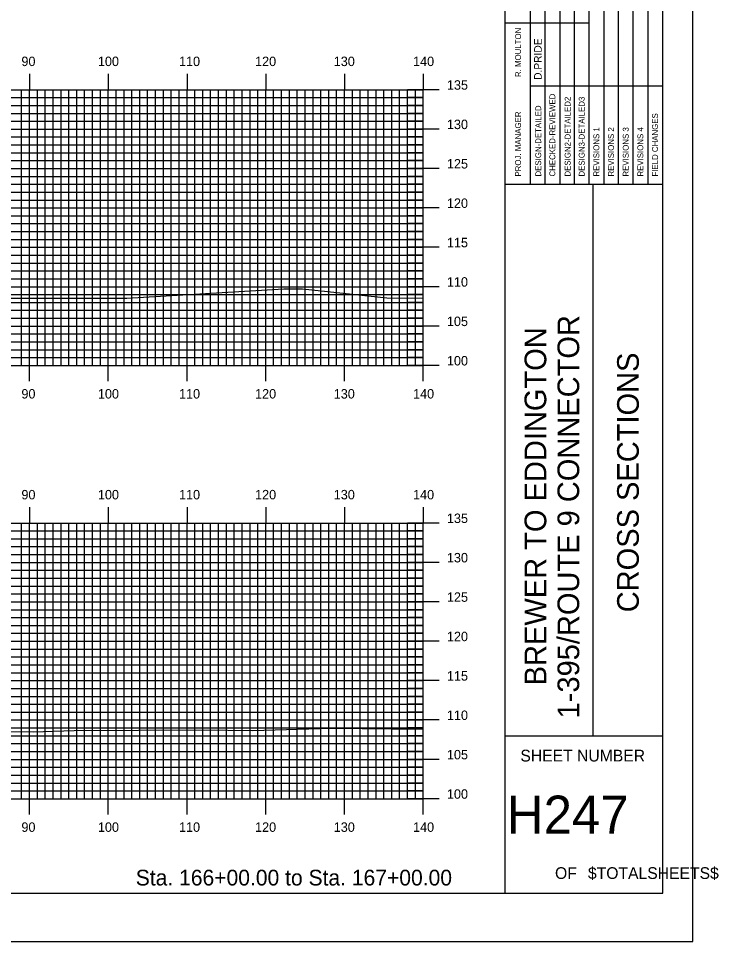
# Model space of a CAD drawing. Extents: x 1781467 to 1781810, y 442591 to 442811.
# Drawn here: x 1781721 to 1781809.9, y 442590.5 to 442707.7 of the extents above; entities that cross this region are included whole.
import ezdxf

# ---------------------------------------------------------------- set-up
doc = ezdxf.new("R2010")
doc.units = 0
for name, color, linetype in [('BORDER', 7, 'Continuous'), ('H_V ANNOTATION', 7, 'Continuous'), ('MAJOR', 7, 'Continuous'), ('MINOR', 7, 'Continuous'), ('PLOT BOUNDARY', 7, 'Continuous'), ('S_Roadway_Centerline', 7, 'Continuous')]:
    doc.layers.add(name, color=color, linetype=linetype)

msp = doc.modelspace()

# ---------------------------------------------------------------- linework, layer by layer
at = {"layer": 'BORDER'}
for p, q in [((1781782.81, 442596.67), (1781782.81, 442806.67)), ((1781782.81, 442686.67), (1781802.81, 442686.67)), ((1781793.99, 442616.67), (1781793.99, 442686.67)), ((1781782.81, 442616.67), (1781802.81, 442616.67))]:
    msp.add_line(p, q, dxfattribs=at)
msp.add_lwpolyline([(1781482.81, 442596.67), (1781802.81, 442596.67), (1781802.81, 442806.67), (1781482.81, 442806.67)], close=True, dxfattribs=at)
for points in [[(1781787.9, 442686.68), (1781787.9, 442721.67)], [(1781789.77, 442721.67), (1781789.77, 442686.68)], [(1781791.63, 442686.68), (1781791.63, 442721.67)], [(1781793.49, 442686.68), (1781793.49, 442721.67)], [(1781795.36, 442686.68), (1781795.36, 442721.67)], [(1781797.22, 442686.68), (1781797.22, 442721.67)], [(1781799.08, 442686.68), (1781799.08, 442721.67)], [(1781800.95, 442686.68), (1781800.95, 442721.67)], [(1781786.04, 442686.68), (1781786.04, 442720.26)], [(1781782.81, 442707.17), (1781786.04, 442707.17)], [(1781786.04, 442707.17), (1781793.49, 442707.17)], [(1781786.04, 442699.17), (1781802.81, 442699.17)]]:
    msp.add_lwpolyline(points, dxfattribs=at)
at = {"layer": 'MAJOR'}
for p, q in [((1781722.41, 442700.67), (1781722.41, 442698.67)), ((1781732.41, 442700.67), (1781732.41, 442698.67)), ((1781742.41, 442700.67), (1781742.41, 442698.67)), ((1781752.41, 442700.67), (1781752.41, 442698.67)), ((1781762.41, 442700.67), (1781762.41, 442698.67)), ((1781772.41, 442700.67), (1781772.41, 442698.67)), ((1781492.41, 442698.67), (1781772.41, 442698.67)), ((1781492.41, 442698.67), (1781772.41, 442698.67)), ((1781722.41, 442663.67), (1781722.41, 442698.67)), ((1781732.41, 442663.67), (1781732.41, 442698.67)), ((1781742.41, 442663.67), (1781742.41, 442698.67)), ((1781752.41, 442663.67), (1781752.41, 442698.67)), ((1781762.41, 442663.67), (1781762.41, 442698.67)), ((1781774.41, 442698.67), (1781770.4, 442698.67)), ((1781772.41, 442663.67), (1781772.41, 442698.67)), ((1781772.41, 442663.67), (1781772.41, 442698.67)), ((1781492.41, 442693.67), (1781772.41, 442693.67)), ((1781774.41, 442693.67), (1781770.4, 442693.67)), ((1781492.41, 442688.67), (1781772.41, 442688.67)), ((1781774.41, 442688.67), (1781770.4, 442688.67)), ((1781492.41, 442683.67), (1781772.41, 442683.67)), ((1781774.41, 442683.67), (1781770.4, 442683.67)), ((1781492.41, 442678.67), (1781772.41, 442678.67)), ((1781774.41, 442678.67), (1781770.4, 442678.67)), ((1781492.41, 442673.67), (1781772.41, 442673.67)), ((1781774.41, 442673.67), (1781770.4, 442673.67)), ((1781492.41, 442668.67), (1781772.41, 442668.67)), ((1781774.41, 442668.67), (1781770.4, 442668.67)), ((1781492.41, 442663.67), (1781772.41, 442663.67)), ((1781492.41, 442663.67), (1781772.41, 442663.67)), ((1781722.41, 442661.66), (1781722.41, 442663.67)), ((1781732.41, 442661.66), (1781732.41, 442663.67)), ((1781742.41, 442661.66), (1781742.41, 442663.67)), ((1781752.41, 442661.66), (1781752.41, 442663.67)), ((1781762.41, 442661.66), (1781762.41, 442663.67)), ((1781774.41, 442663.67), (1781770.4, 442663.67)), ((1781772.41, 442661.66), (1781772.41, 442663.67)), ((1781722.41, 442645.67), (1781722.41, 442643.67)), ((1781732.41, 442645.67), (1781732.41, 442643.67)), ((1781742.41, 442645.67), (1781742.41, 442643.67)), ((1781752.41, 442645.67), (1781752.41, 442643.67)), ((1781762.41, 442645.67), (1781762.41, 442643.67)), ((1781772.41, 442645.67), (1781772.41, 442643.67)), ((1781492.41, 442643.67), (1781772.41, 442643.67)), ((1781492.41, 442643.67), (1781772.41, 442643.67)), ((1781722.41, 442608.67), (1781722.41, 442643.67)), ((1781732.41, 442608.67), (1781732.41, 442643.67)), ((1781742.41, 442608.67), (1781742.41, 442643.67)), ((1781752.41, 442608.67), (1781752.41, 442643.67)), ((1781762.41, 442608.67), (1781762.41, 442643.67)), ((1781774.41, 442643.67), (1781770.4, 442643.67)), ((1781772.41, 442608.67), (1781772.41, 442643.67)), ((1781772.41, 442608.67), (1781772.41, 442643.67)), ((1781492.41, 442638.67), (1781772.41, 442638.67)), ((1781774.41, 442638.67), (1781770.4, 442638.67)), ((1781492.41, 442633.67), (1781772.41, 442633.67)), ((1781774.41, 442633.67), (1781770.4, 442633.67)), ((1781492.41, 442628.67), (1781772.41, 442628.67)), ((1781774.41, 442628.67), (1781770.4, 442628.67)), ((1781492.41, 442623.67), (1781772.41, 442623.67)), ((1781774.41, 442623.67), (1781770.4, 442623.67)), ((1781492.41, 442618.67), (1781772.41, 442618.67)), ((1781774.41, 442618.67), (1781770.4, 442618.67)), ((1781492.41, 442613.67), (1781772.41, 442613.67)), ((1781774.41, 442613.67), (1781770.4, 442613.67)), ((1781492.41, 442608.67), (1781772.41, 442608.67)), ((1781492.41, 442608.67), (1781772.41, 442608.67)), ((1781722.41, 442606.66), (1781722.41, 442608.67)), ((1781732.41, 442606.66), (1781732.41, 442608.67)), ((1781742.41, 442606.66), (1781742.41, 442608.67)), ((1781752.41, 442606.66), (1781752.41, 442608.67)), ((1781762.41, 442606.66), (1781762.41, 442608.67)), ((1781774.41, 442608.67), (1781770.4, 442608.67)), ((1781772.41, 442606.66), (1781772.41, 442608.67))]:
    msp.add_line(p, q, dxfattribs=at)
at = {"layer": 'MINOR'}
for p, q in [((1781721.41, 442663.67), (1781721.41, 442698.67)), ((1781723.41, 442663.67), (1781723.41, 442698.67)), ((1781724.41, 442663.67), (1781724.41, 442698.67)), ((1781725.41, 442663.67), (1781725.41, 442698.67)), ((1781726.41, 442663.67), (1781726.41, 442698.67)), ((1781727.41, 442663.67), (1781727.41, 442698.67)), ((1781728.41, 442663.67), (1781728.41, 442698.67)), ((1781729.41, 442663.67), (1781729.41, 442698.67)), ((1781730.41, 442663.67), (1781730.41, 442698.67)), ((1781731.41, 442663.67), (1781731.41, 442698.67)), ((1781733.41, 442663.67), (1781733.41, 442698.67)), ((1781734.41, 442663.67), (1781734.41, 442698.67)), ((1781735.41, 442663.67), (1781735.41, 442698.67)), ((1781736.41, 442663.67), (1781736.41, 442698.67)), ((1781737.41, 442663.67), (1781737.41, 442698.67)), ((1781738.41, 442663.67), (1781738.41, 442698.67)), ((1781739.41, 442663.67), (1781739.41, 442698.67)), ((1781740.41, 442663.67), (1781740.41, 442698.67)), ((1781741.41, 442663.67), (1781741.41, 442698.67)), ((1781743.41, 442663.67), (1781743.41, 442698.67)), ((1781744.41, 442663.67), (1781744.41, 442698.67)), ((1781745.41, 442663.67), (1781745.41, 442698.67)), ((1781746.41, 442663.67), (1781746.41, 442698.67)), ((1781747.41, 442663.67), (1781747.41, 442698.67)), ((1781748.41, 442663.67), (1781748.41, 442698.67)), ((1781749.41, 442663.67), (1781749.41, 442698.67)), ((1781750.41, 442663.67), (1781750.41, 442698.67)), ((1781751.41, 442663.67), (1781751.41, 442698.67)), ((1781753.41, 442663.67), (1781753.41, 442698.67)), ((1781754.41, 442663.67), (1781754.41, 442698.67)), ((1781755.41, 442663.67), (1781755.41, 442698.67)), ((1781756.41, 442663.67), (1781756.41, 442698.67)), ((1781757.41, 442663.67), (1781757.41, 442698.67)), ((1781758.41, 442663.67), (1781758.41, 442698.67)), ((1781759.41, 442663.67), (1781759.41, 442698.67)), ((1781760.41, 442663.67), (1781760.41, 442698.67)), ((1781761.41, 442663.67), (1781761.41, 442698.67)), ((1781763.41, 442663.67), (1781763.41, 442698.67)), ((1781764.41, 442663.67), (1781764.41, 442698.67)), ((1781765.41, 442663.67), (1781765.41, 442698.67)), ((1781766.41, 442663.67), (1781766.41, 442698.67)), ((1781767.41, 442663.67), (1781767.41, 442698.67)), ((1781768.41, 442663.67), (1781768.41, 442698.67)), ((1781769.41, 442663.67), (1781769.41, 442698.67)), ((1781770.41, 442663.67), (1781770.41, 442698.67)), ((1781771.41, 442663.67), (1781771.41, 442698.67)), ((1781492.41, 442697.67), (1781772.41, 442697.67)), ((1781772.41, 442697.67), (1781770.4, 442697.67)), ((1781492.41, 442696.67), (1781772.41, 442696.67)), ((1781772.41, 442696.67), (1781770.4, 442696.67)), ((1781492.41, 442695.67), (1781772.41, 442695.67)), ((1781772.41, 442695.67), (1781770.4, 442695.67)), ((1781492.41, 442694.67), (1781772.41, 442694.67)), ((1781772.41, 442694.67), (1781770.4, 442694.67)), ((1781492.41, 442692.67), (1781772.41, 442692.67)), ((1781772.41, 442692.67), (1781770.4, 442692.67)), ((1781492.41, 442691.67), (1781772.41, 442691.67)), ((1781772.41, 442691.67), (1781770.4, 442691.67)), ((1781492.41, 442690.67), (1781772.41, 442690.67)), ((1781772.41, 442690.67), (1781770.4, 442690.67)), ((1781492.41, 442689.67), (1781772.41, 442689.67)), ((1781772.41, 442689.67), (1781770.4, 442689.67)), ((1781492.41, 442687.67), (1781772.41, 442687.67)), ((1781492.41, 442686.67), (1781772.41, 442686.67)), ((1781772.41, 442687.67), (1781770.4, 442687.67)), ((1781772.41, 442686.67), (1781770.4, 442686.67)), ((1781492.41, 442685.67), (1781772.41, 442685.67)), ((1781772.41, 442685.67), (1781770.4, 442685.67)), ((1781492.41, 442684.67), (1781772.41, 442684.67)), ((1781772.41, 442684.67), (1781770.4, 442684.67)), ((1781492.41, 442682.67), (1781772.41, 442682.67)), ((1781772.41, 442682.67), (1781770.4, 442682.67)), ((1781492.41, 442681.67), (1781772.41, 442681.67)), ((1781772.41, 442681.67), (1781770.4, 442681.67)), ((1781492.41, 442680.67), (1781772.41, 442680.67)), ((1781492.41, 442679.67), (1781772.41, 442679.67)), ((1781772.41, 442680.67), (1781770.4, 442680.67)), ((1781772.41, 442679.67), (1781770.4, 442679.67)), ((1781492.41, 442677.67), (1781772.41, 442677.67)), ((1781772.41, 442677.67), (1781770.4, 442677.67)), ((1781492.41, 442676.67), (1781772.41, 442676.67)), ((1781772.41, 442676.67), (1781770.4, 442676.67)), ((1781492.41, 442675.67), (1781772.41, 442675.67)), ((1781772.41, 442675.67), (1781770.4, 442675.67)), ((1781492.41, 442674.67), (1781772.41, 442674.67)), ((1781772.41, 442674.67), (1781770.4, 442674.67)), ((1781492.41, 442672.67), (1781772.41, 442672.67)), ((1781772.41, 442672.67), (1781770.4, 442672.67)), ((1781492.41, 442671.67), (1781772.41, 442671.67)), ((1781772.41, 442671.67), (1781770.4, 442671.67)), ((1781492.41, 442670.67), (1781772.41, 442670.67)), ((1781772.41, 442670.67), (1781770.4, 442670.67)), ((1781492.41, 442669.67), (1781772.41, 442669.67)), ((1781772.41, 442669.67), (1781770.4, 442669.67)), ((1781492.41, 442667.67), (1781772.41, 442667.67)), ((1781492.41, 442666.67), (1781772.41, 442666.67)), ((1781772.41, 442667.67), (1781770.4, 442667.67)), ((1781772.41, 442666.67), (1781770.4, 442666.67)), ((1781492.41, 442665.67), (1781772.41, 442665.67)), ((1781772.41, 442665.67), (1781770.4, 442665.67)), ((1781492.41, 442664.67), (1781772.41, 442664.67)), ((1781772.41, 442664.67), (1781770.4, 442664.67)), ((1781721.41, 442608.67), (1781721.41, 442643.67)), ((1781723.41, 442608.67), (1781723.41, 442643.67)), ((1781724.41, 442608.67), (1781724.41, 442643.67)), ((1781725.41, 442608.67), (1781725.41, 442643.67)), ((1781726.41, 442608.67), (1781726.41, 442643.67)), ((1781727.41, 442608.67), (1781727.41, 442643.67)), ((1781728.41, 442608.67), (1781728.41, 442643.67)), ((1781729.41, 442608.67), (1781729.41, 442643.67)), ((1781730.41, 442608.67), (1781730.41, 442643.67)), ((1781731.41, 442608.67), (1781731.41, 442643.67)), ((1781733.41, 442608.67), (1781733.41, 442643.67)), ((1781734.41, 442608.67), (1781734.41, 442643.67)), ((1781735.41, 442608.67), (1781735.41, 442643.67)), ((1781736.41, 442608.67), (1781736.41, 442643.67)), ((1781737.41, 442608.67), (1781737.41, 442643.67)), ((1781738.41, 442608.67), (1781738.41, 442643.67)), ((1781739.41, 442608.67), (1781739.41, 442643.67)), ((1781740.41, 442608.67), (1781740.41, 442643.67)), ((1781741.41, 442608.67), (1781741.41, 442643.67)), ((1781743.41, 442608.67), (1781743.41, 442643.67)), ((1781744.41, 442608.67), (1781744.41, 442643.67)), ((1781745.41, 442608.67), (1781745.41, 442643.67)), ((1781746.41, 442608.67), (1781746.41, 442643.67)), ((1781747.41, 442608.67), (1781747.41, 442643.67)), ((1781748.41, 442608.67), (1781748.41, 442643.67)), ((1781749.41, 442608.67), (1781749.41, 442643.67)), ((1781750.41, 442608.67), (1781750.41, 442643.67)), ((1781751.41, 442608.67), (1781751.41, 442643.67)), ((1781753.41, 442608.67), (1781753.41, 442643.67)), ((1781754.41, 442608.67), (1781754.41, 442643.67)), ((1781755.41, 442608.67), (1781755.41, 442643.67)), ((1781756.41, 442608.67), (1781756.41, 442643.67)), ((1781757.41, 442608.67), (1781757.41, 442643.67)), ((1781758.41, 442608.67), (1781758.41, 442643.67)), ((1781759.41, 442608.67), (1781759.41, 442643.67)), ((1781760.41, 442608.67), (1781760.41, 442643.67)), ((1781761.41, 442608.67), (1781761.41, 442643.67)), ((1781763.41, 442608.67), (1781763.41, 442643.67)), ((1781764.41, 442608.67), (1781764.41, 442643.67)), ((1781765.41, 442608.67), (1781765.41, 442643.67)), ((1781766.41, 442608.67), (1781766.41, 442643.67)), ((1781767.41, 442608.67), (1781767.41, 442643.67)), ((1781768.41, 442608.67), (1781768.41, 442643.67)), ((1781769.41, 442608.67), (1781769.41, 442643.67)), ((1781770.41, 442608.67), (1781770.41, 442643.67)), ((1781771.41, 442608.67), (1781771.41, 442643.67)), ((1781492.41, 442642.67), (1781772.41, 442642.67)), ((1781772.41, 442642.67), (1781770.4, 442642.67)), ((1781492.41, 442641.67), (1781772.41, 442641.67)), ((1781772.41, 442641.67), (1781770.4, 442641.67)), ((1781492.41, 442640.67), (1781772.41, 442640.67)), ((1781772.41, 442640.67), (1781770.4, 442640.67)), ((1781492.41, 442639.67), (1781772.41, 442639.67)), ((1781772.41, 442639.67), (1781770.4, 442639.67)), ((1781492.41, 442637.67), (1781772.41, 442637.67)), ((1781772.41, 442637.67), (1781770.4, 442637.67)), ((1781492.41, 442636.67), (1781772.41, 442636.67)), ((1781772.41, 442636.67), (1781770.4, 442636.67)), ((1781492.41, 442635.67), (1781772.41, 442635.67)), ((1781772.41, 442635.67), (1781770.4, 442635.67)), ((1781492.41, 442634.67), (1781772.41, 442634.67)), ((1781772.41, 442634.67), (1781770.4, 442634.67)), ((1781492.41, 442632.67), (1781772.41, 442632.67)), ((1781772.41, 442632.67), (1781770.4, 442632.67)), ((1781492.41, 442631.67), (1781772.41, 442631.67)), ((1781772.41, 442631.67), (1781770.4, 442631.67)), ((1781492.41, 442630.67), (1781772.41, 442630.67)), ((1781772.41, 442630.67), (1781770.4, 442630.67)), ((1781492.41, 442629.67), (1781772.41, 442629.67)), ((1781772.41, 442629.67), (1781770.4, 442629.67)), ((1781492.41, 442627.67), (1781772.41, 442627.67)), ((1781772.41, 442627.67), (1781770.4, 442627.67)), ((1781492.41, 442626.67), (1781772.41, 442626.67)), ((1781492.41, 442625.67), (1781772.41, 442625.67)), ((1781772.41, 442626.67), (1781770.4, 442626.67)), ((1781772.41, 442625.67), (1781770.4, 442625.67)), ((1781492.41, 442624.67), (1781772.41, 442624.67)), ((1781772.41, 442624.67), (1781770.4, 442624.67)), ((1781492.41, 442622.67), (1781772.41, 442622.67)), ((1781772.41, 442622.67), (1781770.4, 442622.67)), ((1781492.41, 442621.67), (1781772.41, 442621.67)), ((1781772.41, 442621.67), (1781770.4, 442621.67)), ((1781492.41, 442620.67), (1781772.41, 442620.67)), ((1781772.41, 442620.67), (1781770.4, 442620.67)), ((1781492.41, 442619.67), (1781772.41, 442619.67)), ((1781772.41, 442619.67), (1781770.4, 442619.67)), ((1781492.41, 442617.67), (1781772.41, 442617.67)), ((1781772.41, 442617.67), (1781770.4, 442617.67)), ((1781492.41, 442616.67), (1781772.41, 442616.67)), ((1781772.41, 442616.67), (1781770.4, 442616.67)), ((1781492.41, 442615.67), (1781772.41, 442615.67)), ((1781772.41, 442615.67), (1781770.4, 442615.67)), ((1781492.41, 442614.67), (1781772.41, 442614.67)), ((1781772.41, 442614.67), (1781770.4, 442614.67)), ((1781492.41, 442612.67), (1781772.41, 442612.67)), ((1781492.41, 442611.67), (1781772.41, 442611.67)), ((1781772.41, 442612.67), (1781770.4, 442612.67)), ((1781772.41, 442611.67), (1781770.4, 442611.67)), ((1781492.41, 442610.67), (1781772.41, 442610.67)), ((1781772.41, 442610.67), (1781770.4, 442610.67)), ((1781492.41, 442609.67), (1781772.41, 442609.67)), ((1781772.41, 442609.67), (1781770.4, 442609.67))]:
    msp.add_line(p, q, dxfattribs=at)
at = {"layer": 'PLOT BOUNDARY'}
msp.add_lwpolyline([(1781466.62, 442590.55), (1781806.62, 442590.55), (1781806.62, 442810.55), (1781466.62, 442810.55)], close=True, dxfattribs=at)
at = {"layer": 'S_Roadway_Centerline'}
for points in [[(1781598.92, 442672.6), (1781605.77, 442672.68), (1781612.1, 442672.62), (1781618.64, 442672.53), (1781638.86, 442672.72), (1781640.79, 442672.69), (1781642.59, 442672.72), (1781663.6, 442672.44), (1781666.45, 442672.4), (1781683.31, 442672.4), (1781690.43, 442672.33), (1781698.54, 442672.54), (1781707.77, 442672.21), (1781713.19, 442672.21), (1781731.44, 442672.19), (1781734.77, 442672.21), (1781754.69, 442673.38), (1781757.06, 442673.39), (1781767.79, 442672.27), (1781772.41, 442672.23)], [(1781593.57, 442618.68), (1781608.6, 442618.18), (1781616.72, 442617.81), (1781624.5, 442617.74), (1781631.65, 442617.62), (1781646.06, 442617.45), (1781651.08, 442617.46), (1781656.08, 442617.43), (1781674.1, 442617.29), (1781679.32, 442617.38), (1781685.26, 442617.4), (1781691.75, 442617.53), (1781709.96, 442617.43), (1781714.99, 442617.25), (1781722.86, 442617.18), (1781728.07, 442617.32), (1781744.4, 442617.44), (1781750.72, 442617.32), (1781760.76, 442617.61), (1781772.41, 442617.52)]]:
    msp.add_lwpolyline(points, dxfattribs=at)

# ---------------------------------------------------------------- texts
at = {"layer": 'BORDER'}
for s, height, p in [('R. MOULTON', 0.745, (1781784.82, 442700.28)), ('D.PRIDE', 0.969, (1781787.45, 442699.92)), ('CHECKED-REVIEWED', 0.7455, (1781789.17, 442687.65)), ('DESIGN2-DETAILED2', 0.7455, (1781791.11, 442687.65)), ('DESIGN3-DETAILED3', 0.7455, (1781792.9, 442687.65)), ('DESIGN-DETAILED', 0.7455, (1781787.38, 442687.65)), ('PROJ. MANAGER', 0.7455, (1781784.82, 442687.65)), ('FIELD CHANGES', 0.7455, (1781802.21, 442687.65)), ('REVISIONS 1', 0.7455, (1781794.76, 442687.65)), ('REVISIONS 2', 0.7455, (1781796.62, 442687.65)), ('REVISIONS 3', 0.7455, (1781798.49, 442687.65)), ('REVISIONS 4', 0.7455, (1781800.35, 442687.65)), ('1-395/ROUTE 9 CONNECTOR', 2.7557, (1781792.21, 442618.87)), ('BREWER TO EDDINGTON', 2.7557, (1781788.03, 442623.07)), ('CROSS SECTIONS', 2.7557, (1781799.78, 442632.34))]:
    msp.add_text(s, height=height, rotation=90, dxfattribs=at).set_placement(p)
for s, height, p in [('SHEET NUMBER', 1.4905, (1781784.74, 442613.4)), ('H247', 4.839, (1781783.02, 442604.23)), ('OF', 1.491, (1781789.14, 442598.49)), ('$TOTALSHEETS$', 1.4905, (1781793.32, 442598.49))]:
    msp.add_text(s, height=height, dxfattribs=at).set_placement(p)
at = {"layer": 'H_V ANNOTATION'}
for s, height, p in [('90', 1.2, (1781721.38, 442701.67)), ('100', 1.2, (1781731.09, 442701.67)), ('110', 1.2, (1781741.39, 442701.67)), ('120', 1.2, (1781751.05, 442701.67)), ('130', 1.2, (1781761.04, 442701.67)), ('140', 1.2, (1781771.11, 442701.67)), ('135', 1.2, (1781775.41, 442698.67)), ('130', 1.2, (1781775.41, 442693.67)), ('125', 1.2, (1781775.41, 442688.67)), ('120', 1.2, (1781775.41, 442683.67)), ('115', 1.2, (1781775.41, 442678.67)), ('110', 1.2, (1781775.41, 442673.67)), ('105', 1.2, (1781775.41, 442668.67)), ('100', 1.2, (1781775.41, 442663.67)), ('90', 1.2, (1781721.38, 442659.47)), ('100', 1.2, (1781731.09, 442659.47)), ('110', 1.2, (1781741.39, 442659.47)), ('120', 1.2, (1781751.05, 442659.47)), ('130', 1.2, (1781761.04, 442659.47)), ('140', 1.2, (1781771.11, 442659.47)), ('90', 1.2, (1781721.38, 442646.67)), ('100', 1.2, (1781731.09, 442646.67)), ('110', 1.2, (1781741.39, 442646.67)), ('120', 1.2, (1781751.05, 442646.67)), ('130', 1.2, (1781761.04, 442646.67)), ('140', 1.2, (1781771.11, 442646.67)), ('135', 1.2, (1781775.41, 442643.67)), ('130', 1.2, (1781775.41, 442638.67)), ('125', 1.2, (1781775.41, 442633.67)), ('120', 1.2, (1781775.41, 442628.67)), ('115', 1.2, (1781775.41, 442623.67)), ('110', 1.2, (1781775.41, 442618.67)), ('105', 1.2, (1781775.41, 442613.67)), ('100', 1.2, (1781775.41, 442608.67)), ('90', 1.2, (1781721.38, 442604.47)), ('100', 1.2, (1781731.09, 442604.47)), ('110', 1.2, (1781741.39, 442604.47)), ('120', 1.2, (1781751.05, 442604.47)), ('130', 1.2, (1781761.04, 442604.47)), ('140', 1.2, (1781771.11, 442604.47)), ('Sta. 166+00.00 to Sta. 167+00.00', 2.0004, (1781735.9, 442597.66))]:
    msp.add_text(s, height=height, dxfattribs=at).set_placement(p)

doc.saveas('drawing.dxf')
